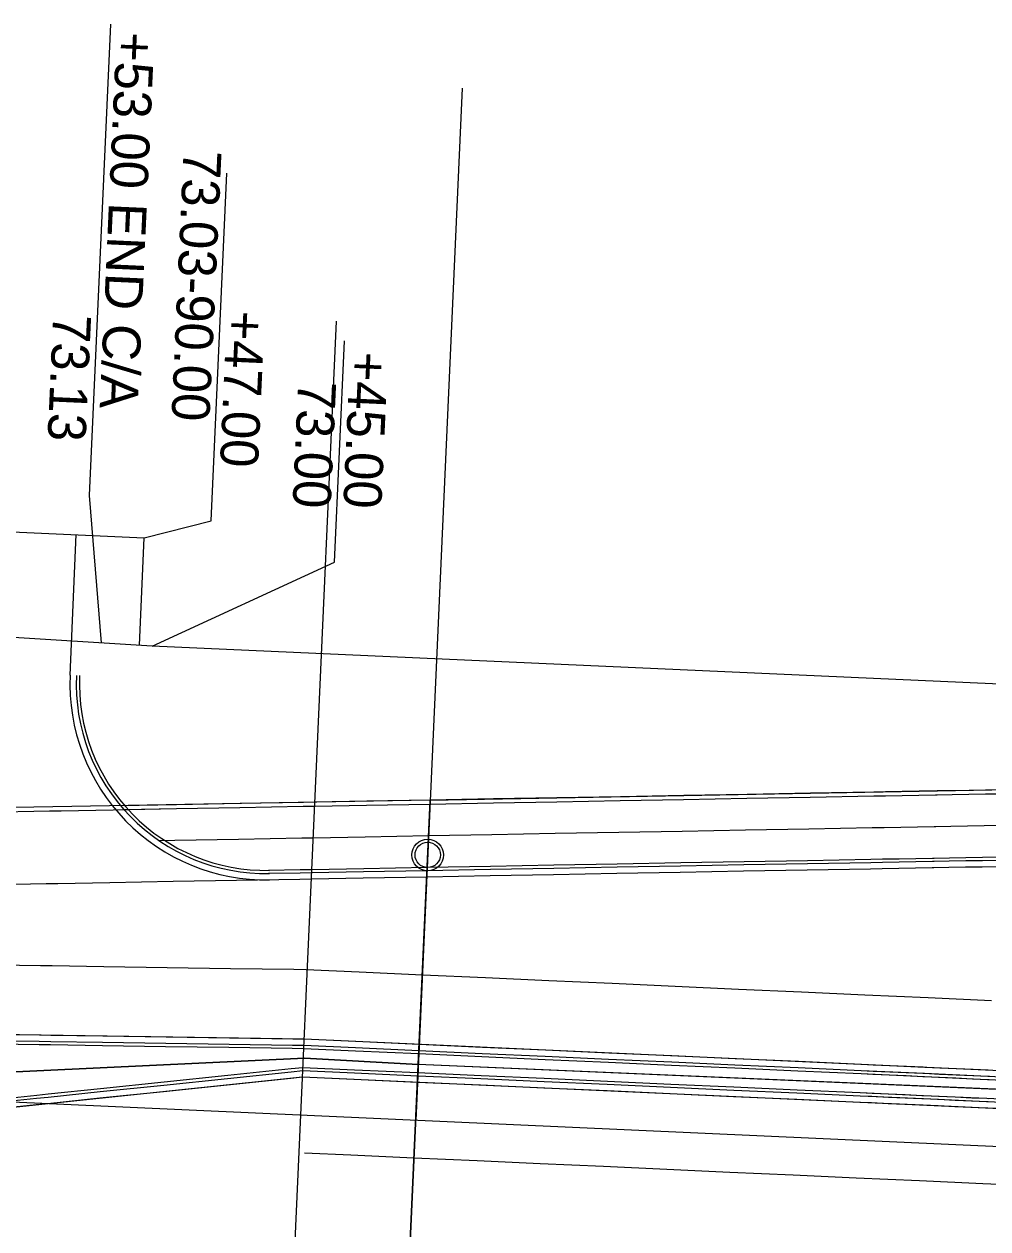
# Model space of a CAD drawing. Extents: x -70 to 701944, y -4 to 666871.
# Drawn here: x 665432.5 to 665584.8, y 656643.3 to 656833.6 of the extents above; entities that cross this region are included whole.
import ezdxf

# ---------------------------------------------------------------- set-up
doc = ezdxf.new("R2010")
doc.units = 0
for name, color, linetype in [('R_Detour', 7, 'Continuous'), ('R_Draft', 7, 'Continuous'), ('R_Drive', 7, 'Continuous'), ('R_Horz Alg', 7, 'Continuous'), ('R_No Plot', 7, 'Continuous'), ('R_Proposed Road', 7, 'Continuous'), ('R_ROW', 7, 'Continuous'), ('R_ROW Annot', 7, 'Continuous'), ('R_Striping', 7, 'Continuous'), ('R_Temp Easement', 7, 'Continuous'), ('R_Water', 7, 'Continuous')]:
    doc.layers.add(name, color=color, linetype=linetype)

msp = doc.modelspace()

# ---------------------------------------------------------------- linework, layer by layer
at = {"layer": 'R_Detour'}
for p in [(665501.72, 656823.51), (665488.17, 656523.44)]:
    msp.add_line(p, (665494.36, 656660.42), dxfattribs=at)
at = {"layer": 'R_Draft'}
msp.add_line((665471.99, 656568.38), (665481.86, 656786.71), dxfattribs=at)
at = {"layer": 'R_Drive'}
msp.add_line((665439.73, 656730.76), (665440.7, 656752.97), dxfattribs=at)
msp.add_lwpolyline([(665586.78, 656711.98), (665584.4, 656711.94), (665581.77, 656711.89), (665579.14, 656711.85), (665576.76, 656711.8), (665576.5, 656711.8), (665573.87, 656711.75), (665571.23, 656711.7), (665568.59, 656711.65), (665566.74, 656711.62), (665556.72, 656711.44), (665546.7, 656711.26), (665536.69, 656711.08), (665526.67, 656710.9), (665516.65, 656710.71), (665506.63, 656710.53), (665496.61, 656710.35), (665486.59, 656710.17), (665478.39, 656710.02), (665476.58, 656709.99), (665466.56, 656709.81), (665456.54, 656709.63), (665448.28, 656709.48)], dxfattribs=at)
for radius in [31, 30, 29.5]:
    msp.add_arc((665470.7, 656729.41), radius, 177.5056, 271.0369, dxfattribs=at)
at = {"layer": 'R_Horz Alg'}
msp.add_line((667725.26, 656559.62), (664961.47, 656684.5), dxfattribs=at)
msp.add_lwpolyline([(665494.13, 656655.42), (665494.36, 656660.42)], dxfattribs=at)
at = {"layer": 'R_No Plot'}
for p, q in [((667813.84, 656555.62), (664810.54, 656691.32)), ((667725.26, 656559.62), (664961.47, 656684.5))]:
    msp.add_line(p, q, dxfattribs=at)
for points in [[(665496.64, 656711.02), (665596.83, 656712.83), (665594.62, 656664.96), (665494.74, 656669.27)], [(665354.5, 656666.74), (665377.65, 656665.54), (665476.78, 656670.25), (665494.74, 656669.27), (665496.64, 656711.02), (665377.33, 656708.92), (665356.45, 656709.86)], [(665354.5, 656666.74), (665352.04, 656612.29), (665372.92, 656611.35), (665456.82, 656605.06), (665491.76, 656602.98), (665494.76, 656669.27), (665476.78, 656670.25), (665377.65, 656665.54)], [(665494.74, 656669.27), (665491.76, 656602.98), (665546.7, 656600.49), (665591.55, 656595.97), (665594.66, 656664.95)]]:
    msp.add_lwpolyline(points, close=True, dxfattribs=at)
msp.add_circle((665496.25, 656702.36), 2.5, dxfattribs=at)
at = {"layer": 'R_Proposed Road'}
for p, q in [((665476.73, 656673.23), (665376.7, 656674.74)), ((665676.53, 656664.2), (665476.73, 656673.23)), ((665476.46, 656667.23), (665375.88, 656656.76)), ((665676.26, 656658.21), (665476.46, 656667.23))]:
    msp.add_line(p, q, dxfattribs=at)
for points in [[(665586.78, 656711.98), (665584.4, 656711.94), (665581.77, 656711.89), (665579.14, 656711.85), (665576.76, 656711.8), (665576.5, 656711.8), (665573.87, 656711.75), (665571.23, 656711.7), (665568.59, 656711.65), (665566.74, 656711.62), (665556.72, 656711.44), (665546.7, 656711.26), (665536.69, 656711.08), (665526.67, 656710.9), (665516.65, 656710.71), (665506.63, 656710.53), (665496.61, 656710.35), (665486.59, 656710.17), (665478.39, 656710.02), (665476.58, 656709.99), (665466.56, 656709.81), (665456.54, 656709.63), (665446.52, 656709.45), (665438.31, 656709.3), (665436.5, 656709.26), (665426.48, 656709.08)], [(665586.81, 656712.65), (665584.43, 656712.61), (665581.8, 656712.56), (665579.17, 656712.51), (665576.79, 656712.47), (665576.53, 656712.46), (665573.9, 656712.42), (665571.26, 656712.37), (665568.62, 656712.32), (665566.77, 656712.29), (665556.75, 656712.11), (665546.73, 656711.92), (665536.72, 656711.74), (665526.7, 656711.56), (665516.68, 656711.38), (665506.66, 656711.2), (665496.64, 656711.02), (665486.62, 656710.84), (665478.42, 656710.69), (665476.61, 656710.66), (665466.59, 656710.47), (665456.57, 656710.29), (665447.71, 656710.13)], [(665586.55, 656706.99), (665584.17, 656706.95), (665581.54, 656706.9), (665578.91, 656706.85), (665576.53, 656706.81), (665576.28, 656706.8), (665573.64, 656706.76), (665571.01, 656706.71), (665568.37, 656706.66), (665566.51, 656706.63), (665556.5, 656706.45), (665546.48, 656706.26), (665536.46, 656706.08), (665526.44, 656705.9), (665516.42, 656705.72), (665506.4, 656705.54), (665496.39, 656705.36), (665486.37, 656705.18), (665478.16, 656705.03), (665476.35, 656704.99), (665466.33, 656704.81), (665456.31, 656704.63), (665453.85, 656704.59)], [(665586.26, 656700.5), (665583.88, 656700.45), (665581.25, 656700.41), (665578.62, 656700.36), (665576.24, 656700.31), (665575.99, 656700.31), (665573.35, 656700.26), (665570.71, 656700.21), (665568.07, 656700.17), (665566.22, 656700.13), (665556.2, 656699.95), (665546.18, 656699.77), (665536.17, 656699.59), (665526.15, 656699.41), (665516.13, 656699.23), (665506.11, 656699.04), (665496.09, 656698.86), (665486.07, 656698.68), (665477.87, 656698.53), (665476.06, 656698.5), (665466.04, 656698.32), (665456.02, 656698.14), (665446, 656697.96), (665437.8, 656697.81), (665435.98, 656697.78), (665425.96, 656697.59)], [(665586.3, 656701.49), (665583.92, 656701.45), (665581.3, 656701.4), (665578.66, 656701.36), (665576.29, 656701.31), (665576.03, 656701.31), (665573.39, 656701.26), (665570.76, 656701.21), (665568.12, 656701.17), (665566.27, 656701.13), (665556.25, 656700.95), (665546.23, 656700.77), (665536.21, 656700.59), (665526.19, 656700.41), (665516.17, 656700.23), (665506.16, 656700.04), (665496.14, 656699.86), (665486.12, 656699.68), (665477.91, 656699.53), (665476.1, 656699.5), (665471.09, 656699.41)], [(665586.33, 656701.99), (665583.95, 656701.95), (665581.32, 656701.9), (665578.69, 656701.86), (665576.31, 656701.81), (665576.05, 656701.81), (665573.42, 656701.76), (665570.78, 656701.71), (665568.14, 656701.67), (665566.29, 656701.63), (665556.27, 656701.45), (665546.25, 656701.27), (665536.23, 656701.09), (665526.22, 656700.91), (665516.2, 656700.72), (665506.18, 656700.54), (665496.16, 656700.36), (665486.14, 656700.18), (665477.94, 656700.03), (665476.12, 656700), (665471.11, 656699.91)], [(665584.81, 656668.34), (665574.82, 656668.79), (665564.83, 656669.25), (665554.84, 656669.7), (665544.85, 656670.15), (665534.86, 656670.6), (665524.87, 656671.05), (665514.88, 656671.5), (665504.89, 656671.95), (665494.9, 656672.41), (665484.91, 656672.86), (665476.73, 656673.23), (665474.92, 656673.25), (665464.91, 656673.41), (665454.91, 656673.56), (665444.91, 656673.71), (665436.71, 656673.83), (665434.9, 656673.86), (665424.9, 656674.01)], [(665584.81, 656668.34), (665582.43, 656668.45), (665579.81, 656668.57), (665577.19, 656668.69), (665574.82, 656668.79), (665574.56, 656668.81), (665571.93, 656668.92), (665569.3, 656669.04), (665566.67, 656669.16), (665564.83, 656669.25), (665554.84, 656669.7), (665544.85, 656670.15), (665534.86, 656670.6), (665524.87, 656671.05), (665514.88, 656671.5), (665504.89, 656671.95), (665494.9, 656672.41), (665484.91, 656672.86), (665476.73, 656673.23), (665474.92, 656673.25), (665464.91, 656673.41), (665454.91, 656673.56), (665444.91, 656673.71), (665436.71, 656673.83), (665434.9, 656673.86), (665424.9, 656674.01)], [(665594.73, 656666.39), (665584.74, 656666.84), (665574.75, 656667.3), (665564.76, 656667.75), (665554.77, 656668.2), (665544.78, 656668.65), (665534.79, 656669.1), (665524.8, 656669.55), (665514.81, 656670), (665504.82, 656670.46), (665494.83, 656670.91), (665484.84, 656671.36), (665476.66, 656671.73), (665474.85, 656671.76), (665464.84, 656671.91), (665454.84, 656672.06), (665444.84, 656672.21), (665436.64, 656672.33), (665434.83, 656672.36), (665424.83, 656672.51)], [(665584.98, 656666.83), (665584.74, 656666.84), (665582.37, 656666.95), (665579.74, 656667.07), (665577.12, 656667.19), (665574.75, 656667.3), (665574.49, 656667.31), (665571.87, 656667.43), (665569.24, 656667.55), (665566.61, 656667.66), (665564.76, 656667.75), (665554.77, 656668.2), (665544.78, 656668.65), (665534.79, 656669.1), (665524.8, 656669.55), (665514.81, 656670), (665504.82, 656670.46), (665494.83, 656670.91), (665484.84, 656671.36), (665476.66, 656671.73), (665474.85, 656671.76), (665464.84, 656671.91), (665454.84, 656672.06), (665444.84, 656672.21), (665436.64, 656672.33), (665434.83, 656672.36), (665424.83, 656672.51)], [(665594.75, 656666.89), (665584.76, 656667.34), (665574.77, 656667.8), (665564.78, 656668.25), (665554.79, 656668.7), (665544.8, 656669.15), (665534.81, 656669.6), (665524.82, 656670.05), (665514.83, 656670.5), (665504.84, 656670.95), (665494.85, 656671.41), (665484.86, 656671.86), (665476.68, 656672.23), (665474.87, 656672.25), (665464.87, 656672.41), (665454.86, 656672.56), (665444.86, 656672.71), (665436.67, 656672.83), (665434.86, 656672.86), (665424.85, 656673.01)], [(665585.01, 656667.33), (665584.76, 656667.34), (665582.39, 656667.45), (665579.77, 656667.57), (665577.14, 656667.69), (665574.77, 656667.8), (665574.52, 656667.81), (665571.89, 656667.93), (665569.26, 656668.04), (665566.63, 656668.16), (665564.78, 656668.25), (665554.79, 656668.7), (665544.8, 656669.15), (665534.81, 656669.6), (665524.82, 656670.05), (665514.83, 656670.5), (665504.84, 656670.95), (665494.85, 656671.41), (665484.86, 656671.86), (665476.68, 656672.23), (665474.87, 656672.25), (665464.87, 656672.41), (665454.86, 656672.56), (665444.86, 656672.71), (665436.67, 656672.83), (665434.86, 656672.86), (665424.85, 656673.01)], [(665594.57, 656662.9), (665584.58, 656663.35), (665574.59, 656663.8), (665564.6, 656664.25), (665554.61, 656664.7), (665544.62, 656665.15), (665534.63, 656665.6), (665524.64, 656666.06), (665514.65, 656666.51), (665504.66, 656666.96), (665494.67, 656667.41), (665484.68, 656667.86), (665476.5, 656668.23), (665474.68, 656668.04), (665464.62, 656666.99), (665454.56, 656665.95), (665444.51, 656664.9), (665436.27, 656664.04), (665434.45, 656663.85), (665424.39, 656662.81)], [(665584.83, 656663.34), (665584.58, 656663.35), (665582.21, 656663.46), (665579.59, 656663.57), (665576.96, 656663.69), (665574.59, 656663.8), (665574.34, 656663.81), (665571.71, 656663.93), (665569.08, 656664.05), (665566.45, 656664.17), (665564.6, 656664.25), (665554.61, 656664.7), (665544.62, 656665.15), (665534.63, 656665.6), (665524.64, 656666.06), (665514.65, 656666.51), (665504.66, 656666.96), (665494.67, 656667.41), (665484.68, 656667.86), (665476.5, 656668.23), (665474.68, 656668.04), (665464.62, 656666.99), (665454.56, 656665.95), (665444.51, 656664.9), (665436.27, 656664.04), (665434.45, 656663.85), (665424.39, 656662.81)], [(665594.59, 656663.4), (665584.6, 656663.85), (665574.61, 656664.3), (665564.62, 656664.75), (665554.63, 656665.2), (665544.64, 656665.65), (665534.65, 656666.1), (665524.66, 656666.56), (665514.67, 656667.01), (665504.68, 656667.46), (665494.69, 656667.91), (665484.7, 656668.36), (665476.52, 656668.73), (665474.7, 656668.54), (665464.64, 656667.49), (665454.59, 656666.45), (665444.53, 656665.4), (665436.29, 656664.54), (665434.47, 656664.35), (665424.41, 656663.31)], [(665584.85, 656663.84), (665584.6, 656663.85), (665582.23, 656663.95), (665579.61, 656664.07), (665576.99, 656664.19), (665574.61, 656664.3), (665574.36, 656664.31), (665571.73, 656664.43), (665569.1, 656664.55), (665566.47, 656664.67), (665564.62, 656664.75), (665554.63, 656665.2), (665544.64, 656665.65), (665534.65, 656666.1), (665524.66, 656666.56), (665514.67, 656667.01), (665504.68, 656667.46), (665494.69, 656667.91), (665484.7, 656668.36), (665476.52, 656668.73), (665474.7, 656668.54), (665464.64, 656667.49), (665454.59, 656666.45), (665444.53, 656665.4), (665436.29, 656664.54), (665434.47, 656664.35), (665424.41, 656663.31)], [(665594.52, 656661.9), (665584.53, 656662.35), (665574.54, 656662.8), (665564.56, 656663.25), (665554.57, 656663.7), (665544.58, 656664.15), (665534.59, 656664.61), (665524.6, 656665.06), (665514.61, 656665.51), (665504.62, 656665.96), (665494.63, 656666.41), (665484.64, 656666.86), (665476.46, 656667.23), (665474.63, 656667.04), (665464.58, 656666), (665454.52, 656664.95), (665444.46, 656663.9), (665436.22, 656663.04), (665434.4, 656662.85), (665424.35, 656661.81)], [(665587.39, 656662.22), (665584.78, 656662.34), (665584.53, 656662.35), (665582.16, 656662.46), (665579.54, 656662.57), (665576.92, 656662.69), (665574.54, 656662.8), (665574.29, 656662.81), (665571.66, 656662.93), (665569.03, 656663.05), (665566.4, 656663.17), (665564.56, 656663.25), (665554.57, 656663.7), (665544.58, 656664.15), (665534.59, 656664.61), (665524.6, 656665.06), (665514.61, 656665.51), (665504.62, 656665.96), (665494.63, 656666.41), (665484.64, 656666.86), (665476.46, 656667.23), (665474.63, 656667.04), (665464.58, 656666), (665454.52, 656664.95), (665444.46, 656663.9), (665436.22, 656663.04), (665434.4, 656662.85), (665424.35, 656661.81)]]:
    msp.add_lwpolyline(points, dxfattribs=at)
at = {"layer": 'R_ROW'}
msp.add_lwpolyline([(668183.45, 656677.29), (668041.7, 656619.63), (667513.59, 656642.26), (667480, 656629.76), (667392.27, 656637.73), (667276.83, 656674.98), (667204.95, 656679.23), (667093.98, 656660.22), (667018.55, 656674.64), (666944.63, 656677.98), (666832.93, 656665.01), (666352.77, 656716.73), (665777.5, 656723.7), (665727.42, 656722.96), (665452.7, 656735.37), (665090.34, 656757.75), (665090.29, 656778.78), (664696.26, 656796.57), (664695.54, 656784.55), (664566.62, 656799.96)], dxfattribs=at)
at = {"layer": 'R_ROW Annot'}
for points in [[(665444.71, 656735.87), (665442.79, 656759.13), (665446.16, 656833.64)], [(665451.47, 656752.45), (665462.03, 656755.14), (665464.51, 656810.08)], [(665452.7, 656735.37), (665481.51, 656748.64), (665483.09, 656783.6)]]:
    msp.add_lwpolyline(points, dxfattribs=at)
at = {"layer": 'R_Striping'}
for points in [[(665585.33, 656679.31), (665575.33, 656679.76), (665565.34, 656680.21), (665555.35, 656680.66), (665545.36, 656681.11), (665535.37, 656681.57), (665525.38, 656682.02), (665515.39, 656682.47), (665505.4, 656682.92), (665495.41, 656683.37), (665485.42, 656683.82), (665477.07, 656684.2), (665475.1, 656684.23), (665465.09, 656684.38), (665455.09, 656684.53), (665445.08, 656684.69), (665436.89, 656684.81), (665435.08, 656684.84), (665425.07, 656684.99)], [(665675.67, 656646.26), (665673.86, 656646.34), (665663.87, 656646.79), (665653.88, 656647.24), (665643.89, 656647.69), (665633.91, 656648.14), (665623.92, 656648.59), (665613.93, 656649.05), (665603.94, 656649.5), (665593.95, 656649.95), (665583.96, 656650.4), (665573.97, 656650.85), (665563.99, 656651.3), (665554, 656651.75), (665544.01, 656652.2), (665534.02, 656652.66), (665524.03, 656653.11), (665514.04, 656653.56), (665504.05, 656654.01), (665494.06, 656654.46), (665484.08, 656654.91), (665476.79, 656655.24)]]:
    msp.add_lwpolyline(points, dxfattribs=at)
at = {"layer": 'R_Temp Easement'}
for p in [(665390.53, 656755.2), (665450.7, 656735.5)]:
    msp.add_line(p, (665451.47, 656752.45), dxfattribs=at)
at = {"layer": 'R_Water'}
msp.add_circle((665496.25, 656702.36), 2, dxfattribs=at)

# ---------------------------------------------------------------- texts
at = {"layer": 'R_ROW Annot'}
for s, p in [('+53.00 END C/A', (665447.1, 656832.48)), ('73.03-90.00', (665457.68, 656813.81)), ('+47.00', (665464.54, 656788.47)), ('73.13', (665437.08, 656787.89)), ('+45.00', (665484.02, 656781.97)), ('73.00', (665475.8, 656777.33))]:
    msp.add_text(s, height=6, rotation=267.4131, dxfattribs=at).set_placement(p)

doc.saveas('drawing.dxf')
